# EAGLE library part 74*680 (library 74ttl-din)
12-bit address COMPARATOR, latch
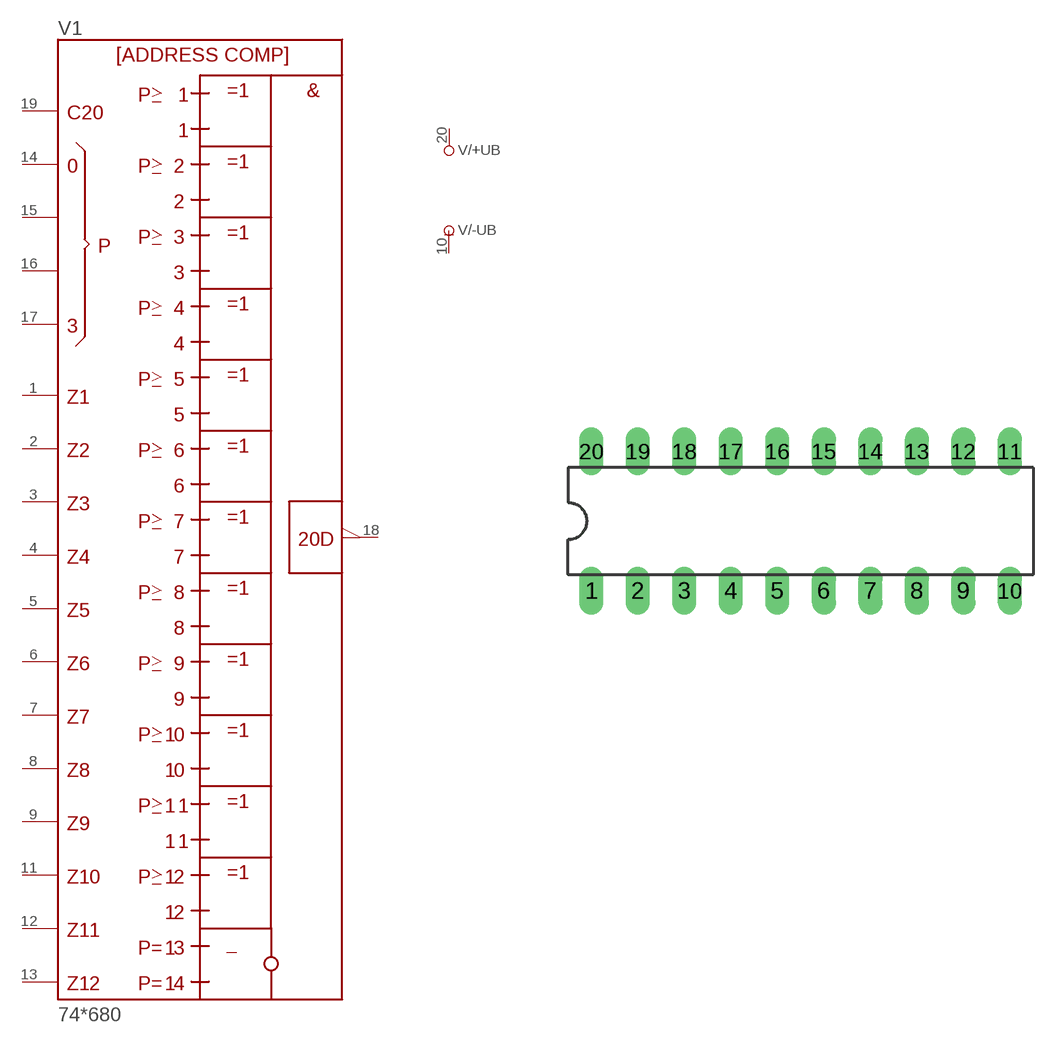
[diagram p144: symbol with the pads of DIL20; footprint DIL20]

Designator prefix V; gates /+UB=+UB /-UB=-UB 1=680

## 74680N  [DIL20]
1  1:A1  in
2  1:A2  in
3  1:A3  in
4  1:A4  in
5  1:A5  in
6  1:A6  in
7  1:A7  in
8  1:A8  in
9  1:A9  in
10  /-UB:-UB  pwr
11  1:A10  in
12  1:A11  in
13  1:A12  in
14  1:P0  in
15  1:P1  in
16  1:P2  in
17  1:P3  in
18  1:Y  out
19  1:C  in
20  /+UB:+UB  pwr

## Footprint DIL20 (pad centres in mm)
Dual In Line Package
drill 0.813 long: 1 -11.43,-3.81; 2 -8.89,-3.81; 3 -6.35,-3.81; 4 -3.81,-3.81; 5 -1.27,-3.81; 6 1.27,-3.81; 7 3.81,-3.81; 8 6.35,-3.81; 9 8.89,-3.81; 10 11.43,-3.81; 11 11.43,3.81; 12 8.89,3.81; 13 6.35,3.81; 14 3.81,3.81; 15 1.27,3.81; 16 -1.27,3.81; 17 -3.81,3.81; 18 -6.35,3.81; 19 -8.89,3.81; 20 -11.43,3.81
